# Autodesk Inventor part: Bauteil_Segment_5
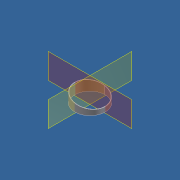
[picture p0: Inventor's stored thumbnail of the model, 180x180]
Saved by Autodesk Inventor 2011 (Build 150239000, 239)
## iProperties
Created: 2009-03
Part Number: Bauteil_Segment_5
Material: S235JR
Document SubType Name: Blech
Designer: Guido Walteich
Density: 7.86 g/cm^3
Flat Pattern Width: 4.7739 cm
Flat Pattern Length: 49.112 cm
Flat Pattern Area: 234.456 cm^2
Description: Blech
Mass: 369.411 g
Surface Area: 345.06 cm^2
Volume: 46.9989 cm^3
Sheet Metal Rule: Standard_mm
Stärke: 3 mm
d0: 160 mm
d6: 48 mm
Gestr_Neutral: 493 mm
Maße: = Ø<d0> x L=<d6> , aus Blech <Stärke> x <d6> x <Gestr_neutral>
Author: Guido Walteich
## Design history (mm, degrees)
node "Skizze1"
node "Konturlasche1"
  sketch "Skizze2"
    geometry: L1 (-98, 0)-(98, 0) reference; L2 (0, -98.1)-(0, 98.6) reference; A1 r 80 centre (0, 0) between (-0.5, 79.998) and (0.5, 79.998); A2 r 0.5 centre (0, 80) between (0.5, 79.998) and (-0.5, 79.998)
    constraints: 5 point on circle, 2 centre point, 2 point on line, 1 midpoint
    dimensions: "d0" = 160 diameter of A1 (= Rohr_D); "d1" = 1 diameter of A2
workplane "Arbeitsebene1"
workplane "Arbeitsebene2"
sketch "Skizze5"
  geometry: L1 (-80, 47.739)-(80, 47.739) reference; L2 (80, 0)-(80, 47.739) reference; L3 (-80, 0)-(-80, 47.739) reference; L4 (80, 0)-(-80, 0) reference; L5 (80, 47.739)-(-80, 15.913); 4 further points
  constraints: 2 end point, 1 point on line
  dimensions: "d18" = 11.25 deg angle of L1 L5 (= WINKEL)
extrude "Extrusion1" cut sketch "Skizze5" stored distance "d19" = 320 (= 2 x Rohr_D); taper "d20" = 0 deg
node "Volumenkörper1"
feature "Grobblech1" dims "d2" = 3 (= BreiteBiegungsfreistellung), "d3" = 1.5 (= TiefeBiegungsfreistellung), "d4" = 6 (= MinimalRest), "d5" = 3 (= Biegeradius), "d6" = 47.73896 (= Länge_5), "d7" = 3 (= Biegeradius), "d8" = 3 (= Wandstärke), "d9" = 12 (= GrößeEckenfreistellung), "d10" = 3 (= Stärke), "d11" = 3 (= JacobiRadiusGröße), "Stärke" = 3 (= Wandstärke), "AbstandVerbindung" = 0.01
feature "Biegung1" dims "d2" = 3 (= BreiteBiegungsfreistellung), "d3" = 1.5 (= TiefeBiegungsfreistellung), "d4" = 6 (= MinimalRest), "d5" = 3 (= Biegeradius), "d7" = 3 (= Biegeradius), "d8" = 3 (= Wandstärke), "Stärke" = 3 (= Wandstärke), "AbstandVerbindung" = 0.01
feature "Ecke1" dims "d8" = 3 (= Wandstärke), "d9" = 12 (= GrößeEckenfreistellung), "d10" = 3 (= Stärke), "d11" = 3 (= JacobiRadiusGröße)
feature "Definition1"
other parameters: "KFaktor" = 4.4, "Biegeradius" = 3 (= Stärke), "BreiteBiegungsfreistellung" = 3 (= Stärke), "TiefeBiegungsfreistellung" = 1.5 (= 0.5 x Stärke), "GrößeEckenfreistellung" = 12 (= 4 x Stärke), "MinimalRest" = 6 (= 2 x Stärke), "Übergangsradius" = 3 (= Biegeradius), "JacobiRadiusGröße" = 3 (= Biegeradius), "Rohr_D" = 160 [user parameter; used in 3 equation terms], "WINKEL_4" = 1.9635 [user parameter], "Länge_5" = 47.73896 [user parameter; used in 1 equation term], "Wandstärke" = 3 [user parameter; used in 3 equation terms], "d12" = 0, "d13" = 0, "Gestr_Neutral" = 493.22994 (= -3.14159 x Wandstärke + 3.14159 x Rohr_D) [user parameter], "WINKEL" = 11.25 deg [user parameter; used in 1 equation term], "Länge_1" = 47.73896 [user parameter], "Länge_2" = 95.47792 [user parameter], "Länge_3" = 95.47792 [user parameter], "Länge_4" = 95.47792 [user parameter], "GES_WINKEL" = 90 deg [user parameter], "ANZ_TEILE" = 39.78874 [user parameter], "Abstandsgröße" = 3 (= Stärke), "Länge_5" = 47.73896, "WINKEL_4" = 1.9635, "Wandstärke" = 3, "Biegeradius" = 3, "BreiteBiegungsfreistellung" = 3, "GrößeEckenfreistellung" = 12, "JacobiRadiusGröße" = 3, "MinimalRest" = 6, "Stärke" = 3, "TiefeBiegungsfreistellung" = 1.5, "Übergangsradius" = 3, "Gestr_Neutral" = 493.22994, "Länge_1" = 47.73896, "Länge_2" = 95.47792, "Länge_3" = 95.47792, "Länge_4" = 95.47792, "WINKEL" = 1.9635, "ANZ_TEILE" = 39.78874, "GES_WINKEL" = 90 deg, "Abstandsgröße" = 3
